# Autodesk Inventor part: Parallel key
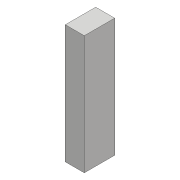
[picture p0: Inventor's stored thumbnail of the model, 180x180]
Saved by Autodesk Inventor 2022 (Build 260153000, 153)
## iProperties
Created: 2016-05
Part Number: Parallel key
Material: Generic
Document SubType Name: Modeling
Designer: CADCIM
Density: 1 g/cm^3
Appearance: Default
Author: CADCIM
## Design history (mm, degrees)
sketch "Sketch1"
  geometry: L1 (0, 0)-(16, 0); L2 (16, 0)-(16, -62.5); L3 (16, -62.5)-(0, -62.5); L4 (0, -62.5)-(0, 0)
  constraints: 8 end point, 2 parallel, 1 horizontal, 1 perpendicular
  dimensions: "d0" = 62.5 distance of L3.end L1.start; "d1" = 16 distance of L2.end L3.end
extrude "Extrusion1" new body sketch "Sketch1" distance "d2" = 10; taper "d3" = 0 deg
body "Solid1"
